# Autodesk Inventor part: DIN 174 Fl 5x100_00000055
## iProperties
Created: 2006-03
Part Number: DIN 174 Fl 5x100_00000055
Material: Default
Document SubType Name: Modeling
Designer: Carlo
Stock Number: DIN 174 Fl 5x100
Mass: 378.849 g
Surface Area: 1601.58 cm^2
Volume: 378.849 cm^3
Density: 1 g/cm^3
G_L: 757.896 mm
G_W: 100.000 mm
G_H: 5.000 mm
AFG_Item: 100 x 5
CSToolsMass: 0.4
CSToolsVolume: 378849.0
CSToolsArea: 1602.0
Author: Carlo
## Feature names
1. AFG_Detailed_DIN 174 Fl 5x100_00000055 [Extrusion]
2. AFG_Simplified_DIN 174 Fl 5x100_00000055 [Extrusion]
3. AFG_EndExtrusion_1 [Extrusion]
4. AFG_EndExtrusion_2 [Extrusion]
5. AFG_StartExtrusion_1 [Extrusion]
6. AFG_StartExtrusion_2 [Extrusion]
